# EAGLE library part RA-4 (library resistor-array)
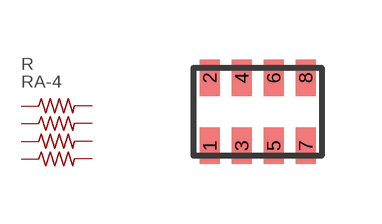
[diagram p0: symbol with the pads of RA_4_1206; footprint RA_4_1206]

Designator prefix R

## RA-41206  [RA_4_1206]
1  1  pas
2  2  pas
3  3  pas
4  4  pas
5  5  pas
6  6  pas
7  7  pas
8  8  pas

## Footprint RA_4_1206 (pad centres in mm)
smd 0.5 x 0.9: 1 -1.2,-0.85; 2 -1.2,0.85; 3 -0.4,-0.85; 4 -0.4,0.85; 5 0.4,-0.85; 6 0.4,0.85; 7 1.2,-0.85; 8 1.2,0.85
